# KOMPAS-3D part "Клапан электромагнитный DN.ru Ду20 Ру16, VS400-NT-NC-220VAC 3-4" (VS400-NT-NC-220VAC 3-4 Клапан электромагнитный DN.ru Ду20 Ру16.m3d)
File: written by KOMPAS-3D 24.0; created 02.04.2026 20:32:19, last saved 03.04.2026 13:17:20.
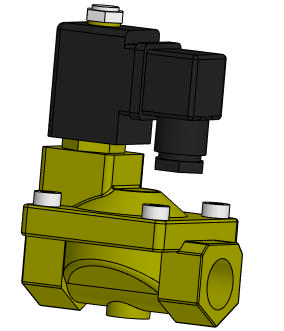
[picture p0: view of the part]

Document properties: Автор: artio; Полное имя файла: C:\Users\artio\OneDrive\Рабочий стол\Клапан электромагнитный DN.ru VS4x-xT-NC-x\VS400-NT-NC\VS400-NT-NC-220VAC 3-4 Клапан электромагнитный DN.ru Ду20 Ру16.m3d

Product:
- Body: Тело 1  | qty 1
    Масса: 1.210539
- Part/product: Клапан электромагнитный DN.ru Ду20 Ру16  | designation VS400-NT-NC-220VAC 3-4
    Масса: 0.954
    Раздел спецификации: Прочие изделия
    Примечание: D130-04662
    additional columns: ef56311e-7521-43dc-8291-0e6108b3d81d; VS400-ET-NC-220VAC 3-4; artio; c; Шероховатость не задана; Да

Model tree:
1. Операция без истории:1

Expressions: VS400-NT-NC-220VAC 3-4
